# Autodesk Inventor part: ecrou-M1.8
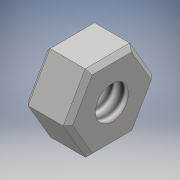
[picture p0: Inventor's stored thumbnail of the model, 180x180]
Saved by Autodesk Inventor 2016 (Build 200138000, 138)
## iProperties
Created: 2018-03
Part Number: ecrou-M1.8
Material: Générique
Document SubType Name: Modeling
Designer: Bruno
Density: 1 g/cm^3
Appearance: Par défaut
Author: Bruno
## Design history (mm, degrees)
sketch "Esquisse1"
  geometry: L1 (-1.003, -1.754)-(-2.021, -0.009); L2 (-2.021, -0.009)-(-1.018, 1.745); L3 (-1.018, 1.745)-(1.003, 1.754); L4 (1.003, 1.754)-(2.021, 0.009); L5 (2.021, 0.009)-(1.018, -1.745); L6 (1.018, -1.745)-(-1.003, -1.754); C1 r 0.75 at (0, 0); 2 further points
  constraints: 12 end point, 2 coincident, 1 centre point, 13 other
  dimensions: "d0" = 1.5 diameter of C1; "d1" = 3.5 distance between parallel lines of L6 L3
extrude "Extrusion1" new body sketch "Esquisse1" distance "d2" = 2; taper "d3" = 0 deg
feature "Filetage1" dims "d7" = 10, "d8" = 0
chamfer "Chanfrein3" distance "d12" = 0.2; stored, may be unused: second distance "d13" = 2, angle "d14" = 45 deg
node "Solide1"
